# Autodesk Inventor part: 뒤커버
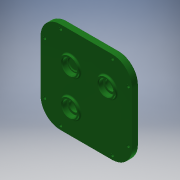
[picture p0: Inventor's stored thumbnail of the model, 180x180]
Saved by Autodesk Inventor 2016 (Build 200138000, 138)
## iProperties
Created: 2016-12
Part Number: 뒤커버
Material: 알루미늄 6061
Document SubType Name: Modeling
Designer: mduedu
Density: 2.71 g/cm^3
Appearance: 매끄러움 - 짙은 산림 녹색
Mass: 485.372 g
Surface Area: 454.562 cm^2
Volume: 179.104 cm^3
Author: mduedu
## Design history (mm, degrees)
sketch "스케치1"
  geometry: L1 (-46, 42)-(-46, -36); L2 (-16, 72)-(62, 72); L3 (92, 42)-(92, -36); L4 (62, -66)-(-16, -66); A1 r 30 centre (-16, -36) between (-46, -36) and (-16, -66); A2 r 30 centre (62, 42) between (92, 42) and (62, 72); A3 r 30 centre (62, -36) between (62, -66) and (92, -36); A4 r 30 centre (-16, 42) between (-16, 72) and (-46, 42); 1 further point
  constraints: 8 end point, 8 point on circle, 8 tangent, 4 centre point, 3 equal radius, 2 perpendicular, 1 horizontal, 1 vertical
  dimensions: "d80" = 30 radius of A2; "d81" = 138 distance between parallel lines of L4 L2; "d82" = 92 distance from line of L3 point (0, 0); "d114" = 46 distance from line of L1 point (0, 0); "d115" = 72 distance from line of L2 point (0, 0)
extrude "돌출1" new body sketch "스케치1" distance "d3" = 10; taper "d4" = 0 deg
sketch "스케치2"
  geometry: C1 r 14 at (0, 26); 1 further point
  constraints: 1 centre point, 1 vertical alignment
  dimensions: "d5" = 28 diameter of C1; "d6" = 26 distance of C1.centre point (0, 0)
extrude "돌출2" join sketch "스케치2" distance "d7" = 3; taper "d8" = 0 deg
sketch "스케치3"
  geometry: C1 r 14 at (0, -28.87); C2 r 14 at (0, 26) reference; C3 r 14 at (54.87, 26); 1 further point
  constraints: 2 centre point, 1 horizontal alignment, 1 vertical alignment
  dimensions: "d9" = 28 diameter of C1; "d69" = 54.87 distance of C1.centre C2.centre; "d83" = 28 diameter of C3; "d84" = 54.87 distance of C3.centre C2.centre
extrude "돌출3" join sketch "스케치3" distance "d11" = 3; taper "d12" = 0 deg
hole "구멍1" diameter "d15" = 22; stored, may be unused: countersink angle "d19" = 90 deg, drill point angle "d21" = 0 deg; dims "d13" = 10, "d14" = 10, "d16" = 6, "d17" = 4, "d18" = 2, "d20" = 7
hole "구멍2" diameter "d24" = 18; stored, may be unused: countersink angle "d28" = 90 deg, drill point angle "d30" = 0 deg; dims "d22" = 10, "d23" = 10, "d25" = 6, "d26" = 4, "d27" = 2, "d29" = 1
hole "구멍3" diameter "d33" = 22; stored, may be unused: countersink angle "d37" = 90 deg, drill point angle "d39" = 0 deg; dims "d31" = 10, "d32" = 10, "d34" = 6, "d35" = 4, "d36" = 2, "d38" = 7
hole "구멍7" diameter "d87" = 22; stored, may be unused: countersink angle "d91" = 90 deg, drill point angle "d93" = 0 deg; dims "d85" = 10, "d86" = 10, "d88" = 6, "d89" = 4, "d90" = 2, "d92" = 7
sketch "스케치4"
  geometry: C1 r 14 at (0, -28.87) reference; C2 r 18 at (0, -28.87); C3 r 14 at (-54.87, 26) reference; C4 r 18 at (-54.87, 26); 1 further point
  constraints: 2 centre point, 2 coincident
  dimensions: "d40" = 36 diameter of C2; "d94" = 36 diameter of C4
extrude "돌출4" join sketch "스케치4" distance "d41" = 4; taper "d42" = 0 deg
hole "구멍4" diameter "d45" = 22; stored, may be unused: countersink angle "d49" = 90 deg, drill point angle "d51" = 0 deg; dims "d43" = 10, "d44" = 10, "d46" = 6, "d47" = 4, "d48" = 2, "d50" = 7
hole "구멍8" diameter "d97" = 22; stored, may be unused: countersink angle "d101" = 90 deg, drill point angle "d103" = 0 deg; dims "d95" = 10, "d96" = 10, "d98" = 6, "d99" = 4, "d100" = 2, "d102" = 7
hole "구멍5" diameter "d54" = 15; stored, may be unused: countersink angle "d58" = 90 deg, drill point angle "d60" = 0 deg; dims "d52" = 10, "d53" = 10, "d55" = 6, "d56" = 4, "d57" = 2, "d59" = 7
hole "구멍9" diameter "d106" = 15; stored, may be unused: countersink angle "d110" = 90 deg, drill point angle "d112" = 0 deg; dims "d104" = 10, "d105" = 10, "d107" = 6, "d108" = 4, "d109" = 2, "d111" = 7
fillet "모깎기1" dims "d61" = 0.3
fillet "모깎기2" dims "d62" = 2
chamfer "모따기1" distance "d63" = 1; stored, may be unused: second distance "d64" = 2, angle "d65" = 45 deg
fillet "모깎기3" dims "d66" = 2
fillet "모깎기4" dims "d67" = 2
fillet "모깎기5" dims "d68" = 2
sketch "스케치5"
  geometry: L1 (-62, 72)-(16, 72) reference; L2 (-92, -36)-(-92, 42) reference; L3 (16, -66)-(-62, -66) reference; L4 (46, 42)-(46, -36) reference; L5 (16, 66)-(-62, 66); L6 (-86, 42)-(-86, -36); L7 (-62, -60)-(16, -60); L8 (40, -36)-(40, 42); A1 r 30 centre (-62, 42) between (-62, 72) and (-92, 42) reference; A2 r 30 centre (-62, -36) between (-92, -36) and (-62, -66) reference; A3 r 30 centre (16, -36) between (16, -66) and (46, -36) reference; A4 r 30 centre (16, 42) between (46, 42) and (16, 72) reference; A5 r 24 centre (-62, 42) between (-62, 66) and (-86, 42); A6 r 24 centre (-62, -36) between (-86, -36) and (-62, -60); A7 r 24 centre (16, -36) between (16, -60) and (40, -36); A8 r 24 centre (16, 42) between (40, 42) and (16, 66)
  constraints: 8 end point, 8 point on circle, 4 centre point, 7 other
  dimensions: "d113" = 6 distance between parallel lines of L6 L2
sketch "스케치6"
  geometry: L1 (16, 66)-(-62, 66) reference; L2 (40, -36)-(40, 42) reference; L3 (-62, -60)-(16, -60) reference; L4 (-86, 42)-(-86, -36) reference; A1 r 24 centre (16, 42) between (40, 42) and (16, 66) reference; A2 r 24 centre (16, -36) between (16, -60) and (40, -36) reference; A3 r 24 centre (-62, -36) between (-86, -36) and (-62, -60) reference; A4 r 24 centre (-62, 42) between (-62, 66) and (-86, 42) reference; 8 further points
  constraints: 8 coincident
hole "구멍6" sketch "스케치6" at (-62, 66), (-86, 42), (-86, -36), (-62, -60), (16, -60), (40, -36), (40, 42), (16, 66) diameter "d71" = 4.5; stored, may be unused: countersink angle "d75" = 90 deg, drill point angle "d77" = 0 deg; dims "d72" = 6, "d73" = 8, "d74" = 4.6, "d76" = 8
node "솔리드1"
